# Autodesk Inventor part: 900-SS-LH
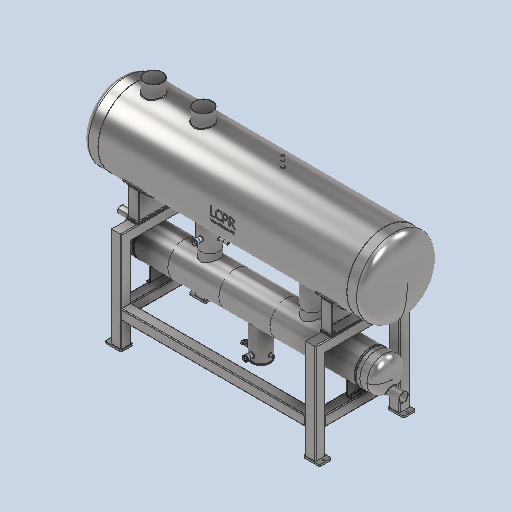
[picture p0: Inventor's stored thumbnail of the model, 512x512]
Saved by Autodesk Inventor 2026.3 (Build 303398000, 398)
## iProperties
Created: 2026-05
Part Number: 900-SS-LH
Material: Generic
Document SubType Name: Modeling
Designer: rva
Density: 1 g/cm^3
Appearance: Default
Author: rva
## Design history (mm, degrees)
derived "LCPR-SS-900-LH.iam"
body "Solid1"
node "Sub-SS-400-200-2646-200-100-75-LH.iam:1::LCPR-SS-400 mm Subc"
node "Sub-SS-400-200-2646-200-100-75-LH.iam:1::LCPR-SS-400 mm Subc"
node "Sub-SS-400-200-2646-200-100-75-LH.iam:1::H1100-R.ipt:2"
node "Sub-SS-400-200-2646-200-100-75-LH.iam:1::1-2 Inch NPT Socket"
node "Sub-SS-400-200-2646-200-100-75-LH.iam:1::Welds"
node "Sub-SS-400-200-2646-200-100-75-LH.iam:1::200 mm Oil Pot Asse"
node "LPR-900-Frame Assembly.iam:1::LCPR-SS-Frame FOOT PLATE 195 x"
node "LPR-900-Frame Assembly.iam:1::LCPR-SS-Frame FOOT PLATE 195 x"
node "LPR-900-Frame Assembly.iam:1::LCPR-SS-Frame FOOT PLATE 195 x"
node "LPR-900-Frame Assembly.iam:1::LCPR-SS-Frame FOOT PLATE 195 x"
node "Nylon Heat Tranfer Spacer 760x125.ipt:1"
node "Nylon Heat Tranfer Spacer 760x125.ipt:2"
node "AS 1111 - Metric M16 x 160:1"
node "AS 1112 (4) - Metric M16:1"
node "AS 1237 (4.2) 16 mm:1"
node "AS 1237 (4.2) 16 mm:2"
node "AS 1111 - Metric M16 x 160:2"
node "AS 1112 (4) - Metric M16:2"
node "AS 1237 (4.2) 16 mm:3"
node "AS 1237 (4.2) 16 mm:4"
node "AS 1111 - Metric M16 x 160:3"
node "AS 1112 (4) - Metric M16:3"
node "AS 1237 (4.2) 16 mm:5"
node "AS 1237 (4.2) 16 mm:6"
node "AS 1111 - Metric M16 x 160:4"
node "AS 1112 (4) - Metric M16:4"
node "AS 1237 (4.2) 16 mm:7"
node "AS 1237 (4.2) 16 mm:8"
node "LCPR-SS-900-3000-200-WELD.iam:1::900 mm LOGO.iam:1::LCPR-LOG"
node "LCPR-SS-900-3000-200-WELD.iam:1::H1100-R.ipt:1"
node "LCPR-SS-900-3000-200-WELD.iam:1::LCPR-SS-900-Leg Assembly.ia"
node "LCPR-SS-900-3000-200-WELD.iam:1::900 mm-SS-Dome End Cap.ipt:"
node "LCPR-SS-900-3000-200-WELD.iam:1::LCPR-SS-900-Leg Assembly.ia"
node "LCPR-SS-900-3000-200-WELD.iam:1::900 mm-SS-Dome End Cap.ipt:"
node "LCPR-SS-900-3000-200-WELD.iam:1::Welds"
node "LCPR-SS-900-LH.iam_Bodies"
